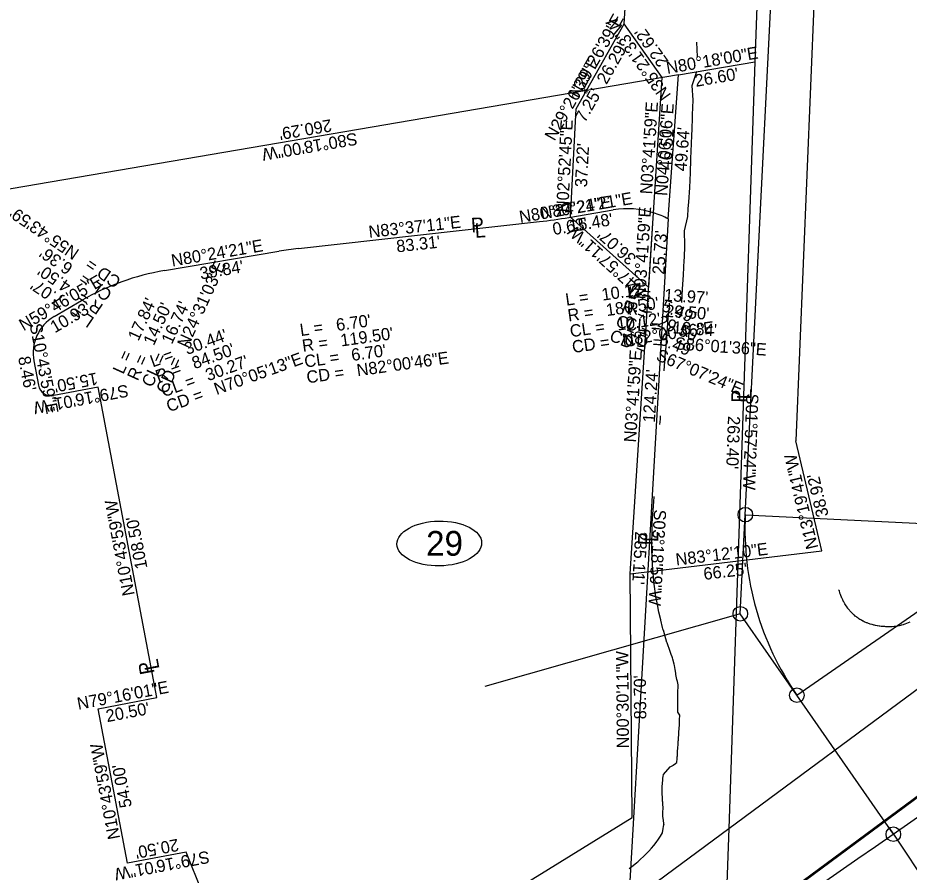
# Model space of a CAD drawing. Extents: x 1145508 to 2262867, y -3126236 to 2021677.
# Drawn here: x 1150120.6 to 1150426.5, y 2019685.5 to 2019978.9 of the extents above; entities that cross this region are included whole.
import ezdxf

# ---------------------------------------------------------------- set-up
doc = ezdxf.new("R2010")
doc.units = 0
for name, color, linetype in [('Default', 7, 'Continuous'), ('DSN_DRFT_Guideline-No-Plot', 7, 'Continuous'), ('DSN_RDWY_Alignment', 7, 'Continuous'), ('DSN_RDWY_Alignment Annotation', 7, 'Continuous'), ('DSN_RDWY_Const Limits', 7, 'Continuous'), ('DSN_ROW_Annotation', 7, 'Continuous'), ('DSN_ROW_Esmnt', 7, 'Continuous'), ('DSN_ROW_Line', 7, 'Continuous'), ('DSN_ROW_Line-Annotation', 7, 'Continuous'), ('DSN_ROW_Prop-Line', 7, 'Continuous'), ('DSN_ROW_Prop-Line-Annotation', 7, 'Continuous'), ('E_Const Align', 7, 'Continuous'), ('EX_QSECTION', 7, 'Continuous'), ('EX_ROW', 7, 'Continuous'), ('EX_ROW_ANNOT', 7, 'Continuous')]:
    doc.layers.add(name, color=color, linetype=linetype)

msp = doc.modelspace()

# ---------------------------------------------------------------- linework, layer by layer
at = {"layer": 'Default'}
msp.add_line((1150568.87, 2019814.51), (1149723.97, 2019188.76), dxfattribs=at)
at = {"layer": 'DSN_RDWY_Alignment'}
for p, q in [((1150370.24, 2019808.25), (1150384.54, 2020092.58)), ((1150368.53, 2019774.23), (1150370.24, 2019808.25)), ((1150387.95, 2019746.24), (1150368.53, 2019774.23)), ((1150127.35, 2019487.87), (1150506.7, 2019769.08)), ((1150421.06, 2019698.5), (1150387.95, 2019746.24)), ((1150421.06, 2019698.5), (1150525.38, 2019541.87))]:
    msp.add_line(p, q, dxfattribs=at)
for points in [[(1150370.24, 2019808.25), (1150447.48, 2019804.37)], [(1150387.95, 2019746.24), (1150440.34, 2019782.58)], [(1150368.53, 2019774.23), (1150280.86, 2019749.2)]]:
    msp.add_lwpolyline(points, dxfattribs=at)
for centre in [(1150370.24, 2019808.25), (1150368.53, 2019774.23), (1150387.95, 2019746.24), (1150421.06, 2019698.5)]:
    msp.add_circle(centre, 2.5, dxfattribs=at)
msp.add_arc((1150470.12, 2019803.23), 100, 177.1209, 214.7418, dxfattribs=at)
at = {"layer": 'DSN_RDWY_Alignment Annotation'}
msp.add_line((1150419.35, 2019700.96), (1150421.06, 2019698.5), dxfattribs=at)
at = {"layer": 'DSN_RDWY_Const Limits'}
for points in [[(1150353.86, 2019965.51), (1150353.61, 2019970.53)], [(1150348.46, 2019881.05), (1150348.69, 2019885.67), (1150349, 2019890.66), (1150349.31, 2019895.65), (1150349.35, 2019896.43), (1150349.52, 2019900.65), (1150349.42, 2019905.66), (1150350.56, 2019910.61), (1150350.68, 2019913.35), (1150350.81, 2019915.6), (1150351.17, 2019920.59), (1150351.38, 2019925.58), (1150351.55, 2019930.3), (1150351.56, 2019930.58), (1150351.75, 2019935.58), (1150351.89, 2019938.58), (1150351.99, 2019940.57), (1150352.15, 2019944.69), (1150352.15, 2019945.57), (1150352.3, 2019950.57), (1150352.03, 2019955.59), (1150353.13, 2019959.05), (1150353.6, 2019960.52)], [(1150342.4, 2019857.68), (1150342.65, 2019860.94), (1150342.78, 2019862.77), (1150343.03, 2019865.93), (1150343.43, 2019870.91), (1150343.67, 2019873.91), (1150343.83, 2019875.9), (1150344.22, 2019879.69), (1150344.28, 2019880.88)], [(1150340.95, 2019839.22), (1150341.09, 2019840.99), (1150341.19, 2019842.21)], [(1150341.9, 2019717.07), (1150341.98, 2019717.71), (1150341.99, 2019717.77), (1150342.08, 2019718.38), (1150342.16, 2019718.97), (1150342.19, 2019719.07), (1150344.47, 2019721.65), (1150344.96, 2019721.86), (1150345.38, 2019722.17), (1150345.47, 2019722.23), (1150346.27, 2019722.82), (1150346.36, 2019722.89), (1150346.78, 2019723.2), (1150346.79, 2019723.21), (1150346.8, 2019723.36), (1150346.8, 2019723.45), (1150346.85, 2019724.23), (1150346.88, 2019724.7), (1150346.9, 2019725.11), (1150346.92, 2019725.42), (1150346.96, 2019725.96), (1150346.96, 2019726.01), (1150347.01, 2019726.91), (1150347.03, 2019727.22), (1150347.07, 2019727.83), (1150347.12, 2019728.48), (1150347.12, 2019728.49), (1150347.15, 2019728.95), (1150347.2, 2019729.75), (1150347.24, 2019730.25), (1150347.24, 2019730.3), (1150347.25, 2019730.5), (1150347.28, 2019730.86), (1150347.29, 2019731.03), (1150347.29, 2019731.05), (1150347.36, 2019732.02), (1150347.38, 2019732.32), (1150347.46, 2019733.5), (1150347.46, 2019733.53), (1150347.47, 2019733.62), (1150347.54, 2019734.66), (1150347.56, 2019734.93), (1150347.57, 2019735.01), (1150347.63, 2019735.9), (1150347.66, 2019736.26), (1150347.67, 2019736.49), (1150347.69, 2019736.76), (1150347.71, 2019737.6), (1150347.69, 2019737.97), (1150347.68, 2019738.28), (1150347.74, 2019738.98), (1150347.8, 2019739.45), (1150347.11, 2019740.43), (1150347.08, 2019740.71), (1150347.05, 2019741.01), (1150347.04, 2019741.86), (1150347.05, 2019742.52), (1150347.05, 2019742.62), (1150347.06, 2019743.1), (1150347.07, 2019743.31), (1150347.08, 2019744.05), (1150347.09, 2019744.78), (1150347.1, 2019745.53), (1150347.1, 2019745.6), (1150347.11, 2019746.29), (1150347.13, 2019747.18), (1150347.14, 2019747.84), (1150347.14, 2019748.02), (1150347.15, 2019748.62), (1150347.16, 2019748.8), (1150347.17, 2019749.43), (1150347.15, 2019749.83), (1150346.92, 2019750.97), (1150346.8, 2019751.6), (1150346.57, 2019752.82), (1150346.46, 2019753.37), (1150346.4, 2019753.72), (1150346.37, 2019753.85), (1150346.14, 2019755.13), (1150345.9, 2019756.45), (1150345.82, 2019756.89), (1150345.42, 2019758.62), (1150345.23, 2019759.11), (1150345.13, 2019759.38), (1150344.8, 2019760.26), (1150344.3, 2019761.66), (1150344.21, 2019761.91), (1150343.63, 2019763.57), (1150343.4, 2019764.23), (1150343.35, 2019764.38), (1150342.94, 2019765.64), (1150342.6, 2019766.83), (1150342.13, 2019768.54), (1150342.11, 2019768.61), (1150341.88, 2019769.45), (1150341.24, 2019772.05), (1150341.23, 2019772.09), (1150340.62, 2019774.75), (1150340.07, 2019777.41), (1150339.86, 2019778.53), (1150339.58, 2019780.09), (1150339.15, 2019782.77), (1150339.05, 2019783.56), (1150338.88, 2019785.07), (1150338.88, 2019785.09), (1150338.84, 2019785.47), (1150338.59, 2019788.18), (1150338.48, 2019789.57), (1150338.39, 2019790.89), (1150338.35, 2019791.69), (1150338.25, 2019793.6), (1150338.2, 2019796.32), (1150338.2, 2019798.3), (1150338.2, 2019799.03), (1150338.23, 2019801.74), (1150338.31, 2019804.44), (1150338.33, 2019804.89), (1150338.45, 2019807.14), (1150338.64, 2019809.84), (1150338.74, 2019811.07), (1150338.76, 2019811.28), (1150338.87, 2019812.64), (1150339.02, 2019814.46)], [(1150426.73, 2019771.37), (1150426.16, 2019771.11), (1150425.58, 2019770.87), (1150424.99, 2019770.65), (1150424.69, 2019770.55), (1150424.39, 2019770.45), (1150423.78, 2019770.27), (1150423.66, 2019770.24), (1150423.16, 2019770.12), (1150423.15, 2019770.11), (1150422.54, 2019769.99), (1150422.46, 2019769.98), (1150421.92, 2019769.9), (1150421.81, 2019769.89), (1150421.59, 2019769.86), (1150421.29, 2019769.83), (1150420.65, 2019769.78), (1150420.6, 2019769.78), (1150420.02, 2019769.75), (1150419.48, 2019769.75), (1150419.39, 2019769.75), (1150418.75, 2019769.76), (1150418.43, 2019769.78), (1150418.12, 2019769.8), (1150418.06, 2019769.81), (1150417.49, 2019769.84), (1150417.43, 2019769.85), (1150417.15, 2019769.87), (1150416.85, 2019769.89), (1150416.46, 2019769.93), (1150416.22, 2019769.96), (1150415.59, 2019770.06), (1150415.53, 2019770.07), (1150414.96, 2019770.18), (1150414.62, 2019770.25), (1150414.34, 2019770.32), (1150414.12, 2019770.38), (1150413.75, 2019770.48), (1150413.71, 2019770.49), (1150413.1, 2019770.68), (1150412.89, 2019770.75), (1150412.49, 2019770.89), (1150412.07, 2019771.05), (1150412.06, 2019771.06), (1150411.89, 2019771.13), (1150411.58, 2019771.26), (1150411.3, 2019771.39), (1150411.16, 2019771.45), (1150411.1, 2019771.48), (1150411.09, 2019771.48), (1150410.72, 2019771.67), (1150410.6, 2019771.73), (1150410.15, 2019771.97), (1150410.14, 2019771.97), (1150410.11, 2019771.99), (1150409.71, 2019772.22), (1150409.61, 2019772.28), (1150409.58, 2019772.3), (1150409.25, 2019772.51), (1150409.12, 2019772.6), (1150409.04, 2019772.66), (1150408.94, 2019772.72), (1150408.64, 2019772.94), (1150408.51, 2019773.04), (1150408.41, 2019773.12), (1150408.16, 2019773.31), (1150408, 2019773.44), (1150407.7, 2019773.7), (1150407.61, 2019773.78), (1150407.51, 2019773.86), (1150407.24, 2019774.11), (1150407.03, 2019774.31), (1150407, 2019774.34), (1150406.86, 2019774.48), (1150406.79, 2019774.54), (1150406.57, 2019774.77), (1150406.36, 2019774.99), (1150406.15, 2019775.23), (1150406.13, 2019775.25), (1150405.95, 2019775.47), (1150405.72, 2019775.74), (1150405.55, 2019775.95), (1150405.5, 2019776.01), (1150405.36, 2019776.2), (1150405.32, 2019776.26), (1150405.17, 2019776.46), (1150404.94, 2019776.79), (1150404.91, 2019776.83), (1150404.86, 2019776.9), (1150404.58, 2019777.33), (1150404.37, 2019777.68), (1150404.25, 2019777.88), (1150404.04, 2019778.27), (1150403.94, 2019778.45), (1150403.88, 2019778.57), (1150403.86, 2019778.61), (1150403.66, 2019779.03), (1150403.45, 2019779.47), (1150403.38, 2019779.61), (1150403.13, 2019780.21), (1150403.06, 2019780.39), (1150403.02, 2019780.49), (1150402.9, 2019780.81), (1150402.73, 2019781.33), (1150402.7, 2019781.42), (1150402.52, 2019782.04), (1150402.35, 2019782.37), (1150402.33, 2019782.45)], [(1150330.41, 2019686.7), (1150331.32, 2019687.41), (1150332.34, 2019688.23), (1150332.99, 2019688.78), (1150333.35, 2019689.08), (1150334.32, 2019689.96), (1150335.28, 2019690.86), (1150336.23, 2019691.77), (1150337.14, 2019692.71), (1150338.03, 2019693.68), (1150338.88, 2019694.68), (1150339.68, 2019695.71), (1150340.42, 2019696.8), (1150341.14, 2019697.89), (1150341.45, 2019698.37), (1150341.79, 2019699.02), (1150342.03, 2019700.43), (1150342.26, 2019701.81), (1150342.31, 2019701.68), (1150342.25, 2019702.21), (1150342.15, 2019703.2), (1150341.99, 2019704.67), (1150341.91, 2019705.48), (1150341.92, 2019706.11), (1150342.01, 2019707.5), (1150342.01, 2019707.57), (1150341.93, 2019708.87), (1150341.89, 2019709.58), (1150341.89, 2019709.63), (1150341.88, 2019709.75), (1150341.87, 2019709.94), (1150341.86, 2019710.19), (1150341.86, 2019710.21), (1150341.84, 2019710.51), (1150341.82, 2019710.88), (1150341.8, 2019711.32), (1150341.78, 2019711.53), (1150341.76, 2019711.81), (1150341.74, 2019712.06), (1150341.74, 2019712.08), (1150341.74, 2019712.09), (1150341.74, 2019712.12), (1150341.74, 2019712.21), (1150341.73, 2019712.34), (1150341.73, 2019712.36), (1150341.73, 2019712.56), (1150341.72, 2019712.81), (1150341.72, 2019712.81), (1150341.72, 2019712.93), (1150341.72, 2019713.12), (1150341.71, 2019713.47), (1150341.71, 2019713.55), (1150341.7, 2019713.87), (1150341.7, 2019714.08), (1150341.69, 2019714.22), (1150341.69, 2019714.31), (1150341.68, 2019714.79), (1150341.68, 2019714.89), (1150341.68, 2019714.92), (1150341.9, 2019717.07)]]:
    msp.add_lwpolyline(points, dxfattribs=at)
at = {"layer": 'DSN_ROW_Esmnt'}
for p, q in [((1150315.73, 2019953.9), (1150328.66, 2019976.79)), ((1150312.17, 2019947.58), (1150315.73, 2019953.9)), ((1150310.3, 2019910.41), (1150312.17, 2019947.58)), ((1150309.67, 2019910.3), (1150310.3, 2019910.41)), ((1150309.67, 2019910.3), (1150309.67, 2019910.3)), ((1150337.09, 2019886.25), (1150310.3, 2019910.41)), ((1150337.09, 2019886.25), (1150338.75, 2019911.93)), ((1150396.51, 2019795.78), (1150387.54, 2019833.65)), ((1150330.73, 2019787.94), (1150396.51, 2019795.78))]:
    msp.add_line(p, q, dxfattribs=at)
at = {"layer": 'DSN_ROW_Line'}
for p, q in [((1150403.47, 2020213.68), (1150387.54, 2019833.65)), ((1150328.66, 2019976.79), (1150336.18, 2020086.55)), ((1150341.75, 2019958.34), (1150328.66, 2019976.79)), ((1150338.75, 2019911.93), (1150341.75, 2019958.34)), ((1150330.73, 2019787.94), (1150338.75, 2019911.93)), ((1150331.46, 2019704.25), (1150330.73, 2019787.94)), ((1150204.85, 2019626.34), (1150331.46, 2019704.25))]:
    msp.add_line(p, q, dxfattribs=at)
at = {"layer": 'DSN_ROW_Line-Annotation'}
msp.add_ellipse((1150265.23, 2019798.36), major_axis=(14.54, 0.23), ratio=0.529773, dxfattribs=at)
at = {"layer": 'DSN_ROW_Prop-Line'}
for p, q in [((1150347.35, 2019959.3), (1150373.57, 2019963.78)), ((1150347.35, 2019959.3), (1150090.79, 2019915.45)), ((1150343.8, 2019909.79), (1150347.35, 2019959.3)), ((1150309.67, 2019910.3), (1150324.94, 2019912.88)), ((1150216.86, 2019899.64), (1150299.65, 2019908.9)), ((1150343.8, 2019909.79), (1150330.2, 2019675.08)), ((1150170.94, 2019892.07), (1150210.22, 2019898.71)), ((1150133.03, 2019876.25), (1150142.47, 2019881.76)), ((1150126.08, 2019861.03), (1150127.66, 2019852.71)), ((1150148.15, 2019852.02), (1150132.92, 2019849.13)), ((1150168.35, 2019745.42), (1150148.15, 2019852.02)), ((1150148.21, 2019741.6), (1150168.35, 2019745.42)), ((1150158.27, 2019688.54), (1150148.21, 2019741.6)), ((1150178.41, 2019692.36), (1150158.27, 2019688.54)), ((1150218.47, 2019592.32), (1150178.41, 2019692.36))]:
    msp.add_line(p, q, dxfattribs=at)
for centre, radius, start, end in [((1150329.86, 2019883.8), 29.5, 72.4592, 99.5943), ((1150279.59, 2020088.28), 180.5, 276.3804, 279.5943), ((1150329.86, 2019883.8), 29.5, 61.7873, 72.4592), ((1150230.14, 2019780.88), 119.5, 96.3804, 99.5943), ((1150185.02, 2019808.75), 84.5, 99.5943, 120.232), ((1150140.33, 2019863.73), 14.5, 120.232, 190.7332), ((1150132.08, 2019853.55), 4.5, 190.7332, 280.7332)]:
    msp.add_arc(centre, radius, start, end, dxfattribs=at)
at = {"layer": 'E_Const Align'}
msp.add_arc((1156951.39, 2010282.18), 11459.16, 121.829445, 126.548983, dxfattribs=at)
msp.add_arc((1156951.39, 2010282.18), 11459.16, 121.829445, 126.548983, dxfattribs=at)
at = {"layer": 'EX_QSECTION'}
for p, q in [((1150382.13, 2020214.47), (1150373.57, 2019963.78)), ((1150373.57, 2019963.78), (1150364.58, 2019700.53)), ((1150364.58, 2019700.53), (1150361.96, 2019623.93))]:
    msp.add_line(p, q, dxfattribs=at)
at = {"layer": 'EX_ROW'}
for p, q in [((1150364.58, 2019700.53), (1150551.02, 2019838.62)), ((1150330.2, 2019675.08), (1150364.58, 2019700.53))]:
    msp.add_line(p, q, dxfattribs=at)

# ---------------------------------------------------------------- texts
at = {"layer": 'DSN_DRFT_Guideline-No-Plot'}
for rotation, p in [(2.9576, (1150328.64, 2019976.76)), (247.5296, (1150341.73, 2019958.37)), (318.0001, (1150341.72, 2019958.34)), (35.1279, (1150315.73, 2019953.87)), (73.8384, (1150312.19, 2019947.56))]:
    msp.add_text('+', height=0.05, rotation=rotation, dxfattribs=at).set_placement(p)
at = {"layer": 'DSN_ROW_Annotation'}
for s, rotation, p in [('N29°26\'39"E', 60.5559, (1150313.03, 2019950.93)), ('N35°21\'33"W', 125.3593, (1150344.92, 2019952.31)), ("22.62'", 125.3593, (1150344.08, 2019963.87)), ("26.29'", 60.5559, (1150322.63, 2019955.74)), ('N80°18\'00"E', 9.6999, (1150343.5, 2019959.56)), ('N29°26\'39"E', 60.5559, (1150304.78, 2019936.33)), ("26.60'", 9.6999, (1150353.28, 2019955.14)), ("7.25'", 60.5559, (1150315.22, 2019942.62)), ('N03°41\'59"E', 86.3003, (1150338.25, 2019918.17)), ('N04°06\'06"E', 85.8984, (1150343.46, 2019917.6)), ("260.29'", 189.6999, (1150227.92, 2019944.06)), ('N02°52\'45"E', 87.1209, (1150309.48, 2019912.01)), ("46.51'", 86.3003, (1150344.81, 2019926.67)), ("49.64'", 85.8984, (1150350.08, 2019926.05)), ('S80°18\'00"W', 189.6999, (1150236.74, 2019939.48)), ("37.22'", 87.1209, (1150315.92, 2019920.6)), ('N55°43\'59"W', 145.7332, (1150141.99, 2019898.96)), ('N80°24\'21"E', 9.5943, (1150293.02, 2019908.4)), ('N80°24\'21"E', 9.5943, (1150300.34, 2019909.64)), ('N03°41\'59"E', 86.3003, (1150335.92, 2019882.13)), ('N83°37\'11"E', 6.3804, (1150241.2, 2019903.27)), ("0.63'", 9.5943, (1150304.48, 2019904.25)), ("15.48'", 9.5943, (1150310.12, 2019905.21)), ('N47°57\'11"W', 137.9532, (1150336.51, 2019885.56)), ("83.31'", 6.3804, (1150250.72, 2019898.29)), ("36.07'", 137.9532, (1150333.16, 2019896.66)), ("25.73'", 86.3003, (1150342.48, 2019890.63)), ('N80°24\'21"E', 9.5943, (1150173.61, 2019893.43)), ("6.36'", 145.7332, (1150139.84, 2019893.82)), ('CD = ', 145.7332, (1150156.35, 2019889.18)), ('N24°31\'03"E', 65.4826, (1150178.88, 2019865.24)), ("39.84'", 9.5943, (1150183.39, 2019889)), ("4.50'", 145.7332, (1150139.23, 2019887.63)), ('N59°46\'05"E', 30.232, (1150122.56, 2019871.2)), ('CL = ', 145.7332, (1150153.28, 2019884.67)), ("7.07'", 145.7332, (1150136.78, 2019882.7)), ("10.12'", 7.9873, (1150321.23, 2019881.72)), ('L = ', 337.1233, (1150329.65, 2019883.3)), ('L = ', 356.0267, (1150329.77, 2019882.57)), ("13.97'", 356.0267, (1150342.27, 2019881.7)), ('R = ', 145.7332, (1150150.2, 2019880.15)), ("17.84'", 65.4826, (1150161.97, 2019867.63)), ('L = ', 7.9873, (1150308.82, 2019879.98)), ("180.50'", 7.9873, (1150322.73, 2019876.42)), ("10.93'", 30.232, (1150133.28, 2019870.49)), ("14.50'", 65.4826, (1150167.25, 2019866.04)), ("16.74'", 65.4826, (1150173.46, 2019866.5)), ('R = ', 337.1233, (1150327.52, 2019878.27)), ('R = ', 356.0267, (1150329.39, 2019877.12)), ("5.49'", 337.1233, (1150341.19, 2019878.43)), ("29.50'", 356.0267, (1150342.64, 2019876.2)), ('L = ', 145.7332, (1150147.13, 2019875.64)), ("6.70'", 7.9873, (1150230.1, 2019871.3)), ('R = ', 7.9873, (1150309.58, 2019874.57)), ('CL = ', 337.1233, (1150325.4, 2019873.24)), ("10.12'", 7.9873, (1150326.44, 2019871.43)), ("29.50'", 337.1233, (1150339.76, 2019873.11)), ('S10°43\'59"E', 280.7332, (1150124.63, 2019873.51)), ('L = ', 7.9873, (1150217.69, 2019869.55)), ('CL = ', 7.9873, (1150310.34, 2019869.17)), ('N82°00\'46"E', 7.9873, (1150328.3, 2019866.17)), ('CL = ', 356.0267, (1150329.01, 2019871.67)), ("13.84'", 356.0267, (1150345.24, 2019870.55)), ("30.44'", 19.9132, (1150178.67, 2019863.06)), ("119.50'", 7.9873, (1150231.6, 2019865.99)), ('CD = ', 337.1233, (1150323.28, 2019868.21)), ('CD = ', 356.0267, (1150328.63, 2019866.23)), ("5.49'", 337.1233, (1150340.39, 2019866.92)), ("84.50'", 19.9132, (1150181.23, 2019858.18)), ('R = ', 7.9873, (1150218.45, 2019864.15)), ('CD = ', 7.9873, (1150311.09, 2019863.76)), ('S86°01\'36"E', 356.0267, (1150345.97, 2019865.02)), ('L = ', 65.4826, (1150156.77, 2019856.23)), ('L = ', 19.9132, (1150166.89, 2019858.79)), ("6.70'", 7.9873, (1150235.32, 2019861)), ('N82°00\'46"E', 7.9873, (1150237.17, 2019855.75)), ('N03°41\'59"E', 86.3003, (1150332.74, 2019832.97)), ('S67°07\'24"E', 337.1233, (1150339.29, 2019861.46)), ("8.46'", 280.7332, (1150120.66, 2019862.25)), ('R = ', 65.4826, (1150161.74, 2019853.96)), ('CL = ', 65.4826, (1150166.71, 2019851.7)), ('CD = ', 65.4826, (1150171.67, 2019849.43)), ("30.27'", 19.9132, (1150185.9, 2019854.06)), ('N70°05\'13"E', 19.9132, (1150188.81, 2019849.31)), ('CL = ', 7.9873, (1150219.21, 2019858.74)), ('R = ', 19.9132, (1150168.75, 2019853.66)), ('CD = ', 7.9873, (1150219.97, 2019853.33)), ("124.24'", 86.3003, (1150339.19, 2019839.77)), ("15.50'", 190.7332, (1150147.59, 2019857.1)), ('CL = ', 19.9132, (1150170.61, 2019848.52)), ('S79°16\'01"W', 190.7332, (1150158.16, 2019853)), ('CD = ', 19.9132, (1150172.47, 2019843.39)), ('N13°19\'41"W', 103.3279, (1150395.32, 2019796.93)), ("38.92'", 103.3279, (1150398.87, 2019807.96)), ('N10°43\'59"W', 100.7332, (1150160.73, 2019780.8)), ('S03°18\'59"W', 266.6837, (1150338.93, 2019810.12)), ("108.50'", 100.7332, (1150165.1, 2019789.98)), ("235.11'", 266.6837, (1150332.48, 2019802.57)), ('N83°12\'10"E', 6.7971, (1150346.58, 2019790.74)), ("66.25'", 6.7971, (1150356.13, 2019785.83)), ('N00°30\'11"W', 90.5031, (1150330.36, 2019728.02)), ('N79°16\'01"E', 10.7332, (1150141.36, 2019741.21)), ("83.70'", 90.5031, (1150336.27, 2019737.99)), ("20.50'", 10.7332, (1150151.22, 2019736.98)), ('N10°43\'59"W', 100.7332, (1150155.72, 2019697.15)), ("54.00'", 100.7332, (1150159.77, 2019708.01)), ("20.50'", 190.7332, (1150175.4, 2019696.98)), ('S79°16\'01"W', 190.7332, (1150185.97, 2019692.88))]:
    msp.add_text(s, height=4.2, rotation=rotation, dxfattribs=at).set_placement(p)
at = {"layer": 'DSN_ROW_Esmnt'}
msp.add_text('b', height=2, dxfattribs=at).set_placement((1150314.73, 2019952.9))
at = {"layer": 'DSN_ROW_Line-Annotation'}
msp.add_text('29', height=8.5, dxfattribs=at).set_placement((1150260.71, 2019794.15))
at = {"layer": 'DSN_ROW_Prop-Line-Annotation'}
for s, rotation, p in [('P', 3.7882, (1150276.26, 2019905.14)), ('L', 3.7882, (1150277.55, 2019903.3)), ('P', 88.7781, (1150370.41, 2019846.64)), ('L', 88.7781, (1150372.36, 2019847.77)), ('P', 88.7781, (1150338.39, 2019797.68)), ('L', 88.7781, (1150340.34, 2019798.8)), ('P', 100.4997, (1150167.56, 2019753.83)), ('L', 100.4997, (1150169.23, 2019755.33))]:
    msp.add_text(s, height=5, rotation=rotation, dxfattribs=at).set_placement(p)
at = {"layer": 'EX_ROW_ANNOT'}
for s, p in [('S01°57\'24"W', (1150370.58, 2019849.89)), ('S01°57\'24"W', (1150370.58, 2019849.89)), ("263.40'", (1150364.31, 2019842.18)), ("263.40'", (1150364.31, 2019842.18))]:
    msp.add_text(s, height=4.2, rotation=268.0433, dxfattribs=at).set_placement(p)

doc.saveas('drawing.dxf')
